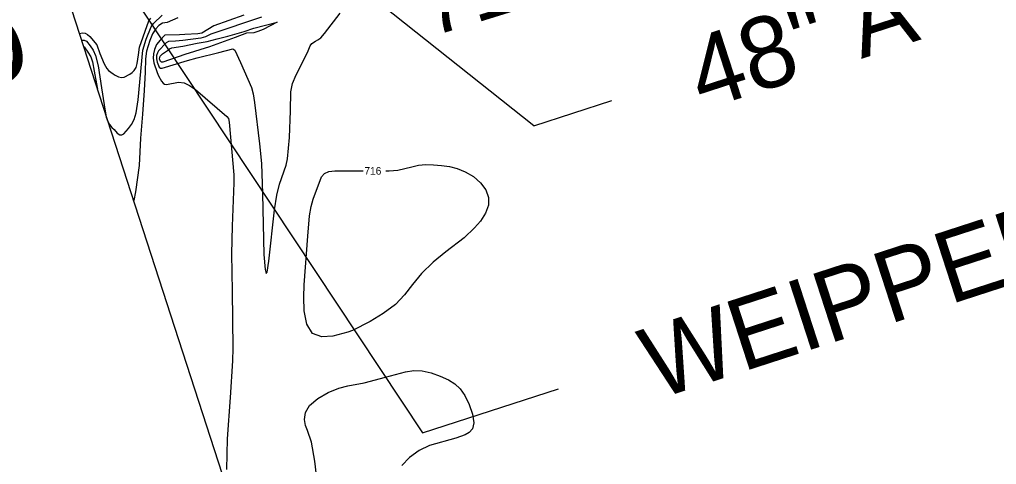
# Model space of a CAD drawing. Extents: x -468563856 to 36492962, y -306094093 to 11899197.
# Drawn here: x 1819091 to 1819604, y 529906 to 530139 of the extents above; entities that cross this region are included whole.
import ezdxf

# ---------------------------------------------------------------- set-up
doc = ezdxf.new("R2010")
doc.units = 0
for name, color, linetype in [('DT_X_Contour_Minor', 7, 'Continuous'), ('DT_X_Terrain_Ground_Line', 7, 'Continuous'), ('Level 19', 7, 'Continuous'), ('Level 40', 7, 'Continuous'), ('SC_Scratch1', 7, 'Continuous')]:
    doc.layers.add(name, color=color, linetype=linetype)

msp = doc.modelspace()

# ---------------------------------------------------------------- linework, layer by layer
at = {"layer": 'DT_X_Contour_Minor'}
for points in [[(1819122.85, 530131.55), (1819124.46, 530131.92), (1819125.88, 530131.79), (1819127.09, 530131.11), (1819128.17, 530130.07), (1819131.84, 530125.68), (1819133.5, 530121.15), (1819135.71, 530115.69), (1819137.09, 530113.22), (1819138.05, 530112.21), (1819140.44, 530110.47), (1819141.52, 530109.8), (1819141.82, 530109.59), (1819143.29, 530108.86), (1819144.8, 530108.54), (1819146.3, 530108.78), (1819149.15, 530110.25), (1819150.43, 530111.09), (1819151.55, 530112.15), (1819152.47, 530113.69), (1819153.13, 530115.87), (1819153.81, 530120.35), (1819154.38, 530124.38), (1819159.19, 530138.29), (1819160.27, 530139.66)], [(1819123.94, 530128.18), (1819125.28, 530128.1), (1819126.44, 530127.51), (1819128.44, 530125.2), (1819130.07, 530122.86), (1819131.24, 530120.03), (1819132.56, 530114.66), (1819134.35, 530103.16), (1819135.69, 530094.15), (1819136.8, 530087.66), (1819137.62, 530085.42), (1819138.63, 530083.79), (1819139.83, 530082.35), (1819140.96, 530081.19), (1819142.63, 530079.4), (1819143.92, 530078.49), (1819145, 530078.37), (1819146, 530078.96), (1819148.59, 530081.69), (1819150.13, 530083.79), (1819151.5, 530086.55), (1819152.5, 530089.99), (1819153.53, 530096.8), (1819156.01, 530122.84), (1819157.86, 530128.64), (1819160.36, 530135.12), (1819161.69, 530136.9), (1819166.16, 530141.28)], [(1819174.44, 530139.75), (1819168.75, 530137.42), (1819166.3, 530136.99), (1819164.48, 530135.84), (1819162.81, 530134), (1819161.13, 530131.46), (1819159.72, 530127.99), (1819157.94, 530122.25), (1819157.49, 530118.23), (1819157.34, 530111.24), (1819156.66, 530101.69), (1819155.84, 530089.36), (1819154.75, 530076.75), (1819154.05, 530062.33), (1819152.19, 530048.57), (1819151.26, 530044.04)], [(1819208.93, 530141.2), (1819193.34, 530135.62), (1819186.95, 530131.72), (1819184.8, 530131.39), (1819178.15, 530131.13), (1819175.24, 530130.89), (1819167.63, 530130.77), (1819165.18, 530128.01), (1819163.25, 530125.74), (1819162.23, 530123.15), (1819161.72, 530121), (1819161.54, 530118.6), (1819161.85, 530116.22), (1819163.49, 530111.22), (1819164.23, 530109.38), (1819165.75, 530106.66), (1819166.63, 530105.53), (1819167.49, 530104.96), (1819168.52, 530104.9), (1819174.79, 530106.01), (1819177.64, 530105.67), (1819180.53, 530104.35), (1819183.62, 530102.14), (1819200.12, 530088.15), (1819201.02, 530086.96), (1819201.24, 530085.12), (1819203.68, 530057.42), (1819203.75, 530053.34), (1819202.86, 530030.49), (1819202.54, 530016.04), (1819202.85, 529996.55), (1819203.22, 529966.55), (1819203.06, 529959.9), (1819201.8, 529940.75), (1819200.3, 529919.04), (1819199.92, 529903)], [(1819218.34, 530140.1), (1819191.64, 530131.27), (1819188.95, 530129.85), (1819186.45, 530129.15), (1819176.96, 530127.99), (1819173.17, 530127.55), (1819169.44, 530127.4), (1819168.26, 530126.67), (1819164.18, 530122.56), (1819163.65, 530121.43), (1819163.28, 530119.98), (1819163.2, 530118.32), (1819163.5, 530116.58), (1819164.67, 530113.86), (1819165.28, 530113.35), (1819166.18, 530113.39), (1819179.39, 530117.37), (1819184.51, 530118.8), (1819195.82, 530121.69), (1819203.3, 530123.54), (1819204.25, 530122.81), (1819207.28, 530116.35), (1819212.99, 530103.19), (1819213.9, 530099.95), (1819214.67, 530095.41), (1819217.27, 530073.7), (1819218.19, 530063.4), (1819218.76, 530047.48), (1819219.46, 530015.66), (1819220.22, 530007.9), (1819220.74, 530005.81), (1819221.27, 530006.51), (1819222.17, 530012.29), (1819225.08, 530039.06), (1819226.34, 530046.87), (1819227.75, 530052.65), (1819231.28, 530062.57), (1819231.94, 530065.9), (1819232.96, 530076.98), (1819233.53, 530091.09), (1819233.71, 530101.03), (1819234.61, 530105.3), (1819236.52, 530109.9), (1819242.45, 530121.56), (1819243.85, 530125.21), (1819244.61, 530126.26), (1819246.6, 530127.61), (1819247.81, 530128.26), (1819249.33, 530129.4), (1819251.34, 530131.53), (1819259.52, 530142.17)], [(1819226.5, 530137.51), (1819219.15, 530133.76), (1819216.35, 530132.57), (1819214.32, 530132.01), (1819210.47, 530131.77), (1819204.42, 530129.55), (1819191.05, 530124.53), (1819178.07, 530120.6), (1819166.52, 530116.54), (1819165.77, 530116.54), (1819165.24, 530116.91), (1819164.75, 530118.31), (1819165.06, 530119.72), (1819166.3, 530120.89), (1819169, 530122.75), (1819170.02, 530123.5), (1819171.31, 530123.99), (1819177.1, 530125), (1819184.51, 530126.56), (1819189.77, 530127.36), (1819195.03, 530128.8), (1819200.69, 530130.12), (1819209.1, 530132.72), (1819214.25, 530134.3), (1819226.5, 530137.51)], [(1819125.1, 530124.61), (1819125.21, 530124.53), (1819127.23, 530121.84), (1819128.7, 530119.43), (1819129.72, 530116.68), (1819130.6, 530111.91), (1819132.11, 530103.36), (1819132.26, 530102.55)], [(1819283.56, 530059.56), (1819285.22, 530059.56), (1819289.71, 530059.95), (1819297.07, 530061.72), (1819300.59, 530062.51), (1819304.42, 530062.87), (1819308.49, 530062.81), (1819312.66, 530062.45), (1819316.8, 530061.84), (1819320.95, 530060.8), (1819325.16, 530059.09), (1819329.37, 530056.55), (1819333.16, 530053.32), (1819335.95, 530049.62), (1819337.33, 530045.64), (1819337.24, 530041.51), (1819335.77, 530037.33), (1819333.1, 530033.26), (1819330, 530029.68), (1819324.62, 530024.42), (1819314.98, 530017.11), (1819308.36, 530011.68), (1819302.12, 530005.76), (1819297.39, 530000.05), (1819293.29, 529994.64), (1819288.49, 529989.51), (1819282.12, 529984.69), (1819275.29, 529980.55), (1819266.08, 529975.82), (1819263.62, 529974.92), (1819255.63, 529972.88), (1819249.95, 529972.46), (1819245.02, 529974.25), (1819242.03, 529979.18), (1819240.7, 529986.12), (1819240.41, 529993.41), (1819240.6, 529999.73), (1819242.65, 530025.38), (1819243.51, 530036.07), (1819244.26, 530040.81), (1819245.33, 530044.72), (1819249.75, 530056.39), (1819251.3, 530058.26), (1819253.63, 530059.27), (1819256.75, 530059.62), (1819271.56, 530059.57)], [(1819247.2, 529899.86), (1819246.31, 529907.33), (1819244.53, 529917.32), (1819242.36, 529923.48), (1819241.42, 529926.08), (1819240.85, 529929.23), (1819241.28, 529932.82), (1819243.44, 529936.57), (1819247.74, 529940.18), (1819253.28, 529943.31), (1819258.82, 529945.62), (1819263.47, 529946.9), (1819272.17, 529948.43), (1819283.32, 529951.4), (1819293.71, 529954.2), (1819298.11, 529954.81), (1819302.53, 529954.64), (1819307.27, 529953.62), (1819312.01, 529951.97), (1819316.27, 529950), (1819319.7, 529947.91), (1819322.49, 529945.34), (1819324.93, 529941.81), (1819327.2, 529937.1), (1819328.93, 529931.97), (1819329.61, 529927.47), (1819328.93, 529924.36), (1819327.25, 529922.42), (1819325.11, 529921.19), (1819320.23, 529919.37), (1819306.44, 529915.51), (1819300.89, 529912.92), (1819295.89, 529909.29), (1819291.85, 529904.99)]]:
    msp.add_lwpolyline(points, dxfattribs=at)
at = {"layer": 'DT_X_Terrain_Ground_Line'}
msp.add_line((1819362.19, 529394.35), (1818754.73, 531265.42), dxfattribs=at)
at = {"layer": 'Level 40'}
for q in [(1819123.28, 530271.85), (1819402.01, 530096.46)]:
    msp.add_line((1819361.17, 530083.2), q, dxfattribs=at)
msp.add_lwpolyline([(1819122.3, 530194.36), (1819302.66, 529922.19), (1819373.99, 529945.35)], dxfattribs=at)
at = {"layer": 'SC_Scratch1'}
msp.add_lwpolyline([(1818754.73, 531265.42), (1818680.3, 532625.97), (1826365.04, 535120.88), (1826839.27, 533890.33), (1827446.85, 532018.88), (1827532.11, 531348.3), (1819682.53, 528840.07), (1819362.19, 529394.35)], close=True, dxfattribs=at)

# ---------------------------------------------------------------- texts
at = {"layer": 'DT_X_Terrain_Ground_Line'}
msp.add_text('MATCH LINE                  STA. 1525+00', height=46.8, rotation=107.9864, dxfattribs=at).set_placement((1819311.09, 529448.74))
at = {"layer": 'Level 19'}
for s, height, rotation, p in [('715', 33, 17.2575, (1819306.97, 530129.72)), ('716', 4, 359.9894, (1819272.21, 530057.56))]:
    msp.add_text(s, height=height, rotation=rotation, dxfattribs=at).set_placement(p)
at = {"layer": 'Level 40'}
for s, p in [('48" A', (1819449.57, 530091.21)), ('WEIPPERT DT.', (1819425.3, 529939.42))]:
    msp.add_text(s, height=37.5, rotation=17.9864, dxfattribs=at).set_placement(p)

doc.saveas('drawing.dxf')
